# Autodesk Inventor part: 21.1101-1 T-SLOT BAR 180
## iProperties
Created: 2006-12
Part Number: 21.1101-1 T-SLOT BAR 180
Material: Steel
Document SubType Name: Modeling
Designer: Andy Moles
Density: 7.85 g/cm^3
Author: Andy Moles
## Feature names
1. Extrusion1
2. Hole1
